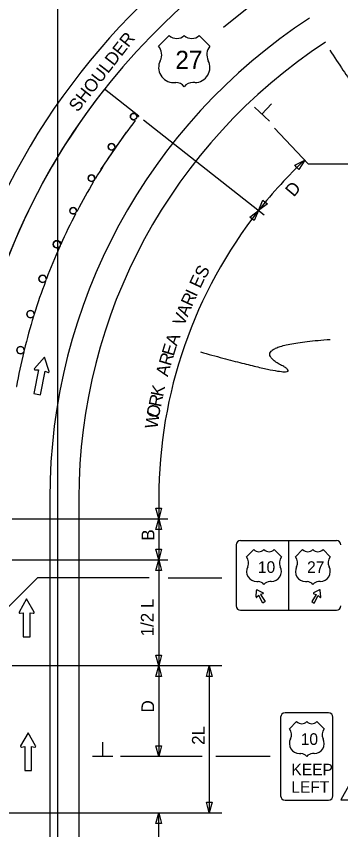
# Model space of a CAD drawing. Extents: x 16486 to 19505, y 5576 to 6998.
# Drawn here: x 16981.9 to 17160.6, y 6297.8 to 6745.9 of the extents above; entities that cross this region are included whole.
import ezdxf

# ---------------------------------------------------------------- set-up
doc = ezdxf.new("R2010")
doc.units = 0
for name, color, linetype in [('ALI_LEGAL_EX', 7, 'Continuous'), ('MT_SCRATCH_LEVEL_A', 7, 'Continuous'), ('MT_SCRATCH_LEVEL_E', 7, 'Continuous'), ('PAVT_EDGE_EX', 7, 'Continuous'), ('TRAFFIC_SIGNS_PR', 7, 'Continuous'), ('TYPICAL_EX', 7, 'Continuous'), ('TYPICAL_TEXT_DIMEN_PR', 7, 'Continuous')]:
    doc.layers.add(name, color=color, linetype=linetype)

msp = doc.modelspace()

# ---------------------------------------------------------------- linework, layer by layer
at = {"layer": 'ALI_LEGAL_EX'}
for p, q in [((17004.68, 6974.12), (17004.68, 6155.98)), ((17004.68, 6922.21), (17004.68, 6058.3))]:
    msp.add_line(p, q, dxfattribs=at)
for points in [[(17096.1, 6739.95), (17115.56, 6755.65)], [(17028.47, 6661.47), (17042.59, 6682.1)], [(17028.47, 6661.47), (17042.59, 6682.1)]]:
    msp.add_lwpolyline(points, dxfattribs=at)
at = {"layer": 'MT_SCRATCH_LEVEL_A'}
for points in [[(17049.36, 6690.98), (17030.51, 6705.83)], [(17047.47, 6688.56), (17047.02, 6688.91)], [(17048.36, 6690.77), (17049.21, 6690.79)], [(17036.22, 6674.06), (17036.65, 6673.76)], [(17035.5, 6672.09), (17035.08, 6672.38)], [(17025.1, 6656.76), (17025.49, 6656.52)], [(17024.54, 6654.94), (17024.15, 6655.17)], [(17015.04, 6638.82), (17015.4, 6638.63)], [(17014.63, 6637.16), (17014.27, 6637.35)], [(17006.27, 6620.31), (17006.43, 6620.24)], [(17005.76, 6618.76), (17005.6, 6618.83)], [(16998.06, 6599.94), (16997.94, 6599.98)], [(16998.43, 6601.3), (16998.55, 6601.25)], [(16991.49, 6580.69), (16991.4, 6580.72)], [(16991.75, 6581.84), (16991.84, 6581.82)], [(16986.25, 6562.02), (16986.31, 6562.01)], [(16986.08, 6561.09), (16986.02, 6561.1)], [(16981.95, 6541.91), (16981.99, 6541.9)]]:
    msp.add_lwpolyline(points, dxfattribs=at)
for centre, radius, start, end in [((17316.4, 6480.53), 364, 141.7598, 180), ((17046.56, 6690.66), 1.8, 3.5129, 180), ((17316.4, 6480.53), 340, 142.2759, 145.3661), ((17046.56, 6690.66), 1.8, 180, 284.5518), ((17316.4, 6480.53), 340, 141.7598, 141.7992), ((17034.42, 6674.06), 1.8, 0, 180), ((17034.42, 6674.06), 1.8, 180, 291.4148), ((17316.4, 6480.53), 340, 145.7074, 148.8275), ((17023.3, 6656.76), 1.8, 0, 180), ((17023.3, 6656.76), 1.8, 180, 298.2766), ((17316.4, 6480.53), 340, 149.1383, 152.2895), ((17013.24, 6638.82), 1.8, 0, 180), ((17013.24, 6638.82), 1.8, 180, 305.1374), ((17316.4, 6480.53), 340, 152.5687, 155.7382), ((17004.27, 6620.31), 2, 0, 180), ((17004.27, 6620.31), 2, 180, 312.0242), ((17316.4, 6480.53), 340, 156.0121, 159.2032), ((16996.43, 6601.3), 2, 0, 180), ((17316.4, 6480.53), 340, 159.4399, 162.6687), ((16996.43, 6601.3), 2, 180, 318.8797), ((16989.75, 6581.84), 2, 0, 180), ((17316.4, 6480.53), 340, 162.8672, 166.1345), ((16989.75, 6581.84), 2, 180, 325.7344), ((16984.25, 6562.02), 2, 0, 180), ((16984.25, 6562.02), 2, 180, 332.5884), ((17316.4, 6480.53), 340, 166.2942, 169.6006)]:
    msp.add_arc(centre, radius, start, end, dxfattribs=at)
at = {"layer": 'MT_SCRATCH_LEVEL_E'}
for p, q in [((16997.4, 6558.21), (16991.97, 6551.9)), ((17000.07, 6550.31), (16997.4, 6558.21)), ((16994.11, 6551.1), (16991.55, 6538.09)), ((16992.31, 6551.13), (16994.11, 6551.1)), ((16995.23, 6537.37), (16997.78, 6550.38)), ((16997.78, 6550.38), (16999.47, 6549.73)), ((16991.55, 6538.09), (16995.23, 6537.37)), ((16987.65, 6424.96), (16983.54, 6417.72)), ((16991.8, 6417.72), (16987.65, 6424.96)), ((16984.02, 6417.03), (16985.8, 6417.35)), ((16985.8, 6417.35), (16985.8, 6404.09)), ((16989.54, 6404.09), (16989.54, 6417.35)), ((16989.54, 6417.35), (16991.32, 6417.03)), ((16985.8, 6404.09), (16989.54, 6404.09)), ((16988.45, 6351.23), (16984.34, 6343.99)), ((16992.6, 6343.99), (16988.45, 6351.23)), ((16984.82, 6343.31), (16986.6, 6343.62)), ((16986.6, 6343.62), (16986.6, 6330.36)), ((16990.34, 6330.36), (16990.34, 6343.62)), ((16990.34, 6343.62), (16992.12, 6343.31)), ((16986.6, 6330.36), (16990.34, 6330.36))]:
    msp.add_line(p, q, dxfattribs=at)
for centre, start, end in [((16992.32, 6551.6), 139.3091, 268.8481), ((16999.62, 6550.16), 248.9205, 18.6574), ((16983.95, 6417.49), 150.4248, 279.9638), ((16991.39, 6417.49), 260.0362, 29.7731), ((16984.75, 6343.76), 150.4248, 279.9638), ((16992.19, 6343.76), 260.0362, 29.7731)]:
    msp.add_arc(centre, 0.463, start, end, dxfattribs=at)
at = {"layer": 'PAVT_EDGE_EX'}
for p, q in [((17000.4, 6480.53), (17000.4, 6125.9)), ((17016.4, 6480.53), (17016.4, 6125.9))]:
    msp.add_line(p, q, dxfattribs=at)
for radius, start, end in [(380, 123.1879, 163.0483), (364, 123.1879, 180), (316, 123.1879, 180), (300, 123.1879, 180), (300, 180, 180.00000277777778)]:
    msp.add_arc((17316.4, 6480.53), radius, start, end, dxfattribs=at)
at = {"layer": 'TRAFFIC_SIGNS_PR'}
for p, q in [((17102.95, 6454.67), (17102.95, 6421.07)), ((17105.35, 6457.07), (17158.15, 6457.07)), ((17131.75, 6457.07), (17131.75, 6418.67)), ((17113.93, 6426.02), (17114.22, 6429.65)), ((17114.59, 6429.86), (17117.87, 6428.3)), ((17148.92, 6429.86), (17145.64, 6428.3)), ((17149.57, 6426.02), (17149.29, 6429.65)), ((17105.35, 6418.67), (17158.15, 6418.67)), ((17127.49, 6359.71), (17127.49, 6316.51)), ((17153.89, 6362.11), (17129.89, 6362.11)), ((17156.29, 6316.51), (17156.29, 6359.71)), ((17129.89, 6314.11), (17153.89, 6314.11))]:
    msp.add_line(p, q, dxfattribs=at)
for points in [[(17117.83, 6427.81), (17116.42, 6427.42), (17118.93, 6423.44), (17117.6, 6422.67), (17115.41, 6426.84), (17114.37, 6425.82)], [(17145.68, 6427.81), (17147.09, 6427.42), (17144.57, 6423.44), (17145.9, 6422.67), (17148.09, 6426.84), (17149.13, 6425.82)]]:
    msp.add_lwpolyline(points, dxfattribs=at)
for centre, radius in [((17046.56, 6690.66), 1.8), ((17034.42, 6674.06), 1.8), ((17023.3, 6656.76), 1.8), ((17013.24, 6638.82), 1.8), ((17004.27, 6620.31), 2), ((16996.43, 6601.3), 2), ((16989.75, 6581.84), 2), ((16984.25, 6562.02), 2)]:
    msp.add_circle(centre, radius, dxfattribs=at)
for centre, radius, start, end in [((17105.35, 6454.67), 2.4, 90, 180), ((17105.35, 6454.67), 2.4, 90, 180), ((17158.15, 6454.67), 2.4, 0, 90), ((17114.47, 6429.63), 0.26, 64.4823, 175.5177), ((17117.75, 6428.06), 0.26, 285.9885, 64.4823), ((17145.75, 6428.06), 0.26, 115.5177, 254.0115), ((17149.03, 6429.63), 0.26, 4.4823, 115.5177), ((17114.19, 6426), 0.26, 175.5177, 314.0115), ((17149.31, 6426), 0.26, 225.9885, 4.4823), ((17105.35, 6421.07), 2.4, 180, 270), ((17158.15, 6421.07), 2.4, 270, 0), ((17129.89, 6359.71), 2.4, 90, 180), ((17153.89, 6359.71), 2.4, 0, 90), ((17129.89, 6316.51), 2.4, 180, 270), ((17153.89, 6316.51), 2.4, 270, 0)]:
    msp.add_arc(centre, radius, start, end, dxfattribs=at)
at = {"layer": 'TYPICAL_EX'}
for p, q in [((17060.28, 6729.51), (17066.18, 6735.4)), ((17088.58, 6729.51), (17082.68, 6735.4)), ((17068.53, 6709.45), (17069.71, 6709.45)), ((17080.33, 6709.45), (17079.15, 6709.45)), ((17108.7, 6448.07), (17112.7, 6452.07)), ((17127.9, 6448.07), (17123.9, 6452.07)), ((17135.6, 6448.07), (17139.6, 6452.07)), ((17154.8, 6448.07), (17150.8, 6452.07)), ((17114.3, 6434.46), (17115.1, 6434.46)), ((17122.31, 6434.46), (17121.51, 6434.46)), ((17141.2, 6434.46), (17142, 6434.46)), ((17149.21, 6434.46), (17148.41, 6434.46)), ((17132.29, 6353.31), (17136.29, 6357.31)), ((17151.49, 6353.31), (17147.49, 6357.31)), ((17137.88, 6339.7), (17138.68, 6339.7)), ((17145.89, 6339.7), (17145.09, 6339.7))]:
    msp.add_line(p, q, dxfattribs=at)
for centre, radius, start, end in [((17070.3, 6739.69), 5.96, 226.1404, 313.8596), ((17078.56, 6739.69), 5.96, 226.1404, 313.8596), ((17054.69, 6724.78), 7.31, 333.0977, 40.1936), ((17094.17, 6724.78), 7.31, 139.8064, 206.9023), ((17068.54, 6717.69), 8.24, 152.6698, 269.9013), ((17080.32, 6717.69), 8.24, 270.0987, 27.3302), ((17069.72, 6703.54), 5.91, 37.1038, 90.1385), ((17079.14, 6703.54), 5.91, 89.8615, 142.8962), ((17115.5, 6454.99), 4.04, 226.1404, 313.8596), ((17121.1, 6454.99), 4.04, 226.1404, 313.8596), ((17142.4, 6454.99), 4.04, 226.1404, 313.8596), ((17148, 6454.99), 4.04, 226.1404, 313.8596), ((17104.91, 6444.87), 4.96, 333.0977, 40.1936), ((17131.69, 6444.87), 4.96, 139.8064, 206.9023), ((17131.81, 6444.87), 4.96, 333.0977, 40.1936), ((17158.59, 6444.87), 4.96, 139.8064, 206.9023), ((17114.31, 6440.06), 5.59, 152.6698, 269.9013), ((17122.3, 6440.06), 5.59, 270.0987, 27.3302), ((17141.21, 6440.06), 5.59, 152.6698, 269.9013), ((17149.2, 6440.06), 5.59, 270.0987, 27.3302), ((17115.11, 6430.46), 4.01, 37.1038, 90.1385), ((17121.5, 6430.46), 4.01, 89.8615, 142.8962), ((17142.01, 6430.46), 4.01, 37.1038, 90.1385), ((17148.4, 6430.46), 4.01, 89.8615, 142.8962), ((17139.09, 6360.22), 4.04, 226.1404, 313.8596), ((17144.69, 6360.22), 4.04, 226.1404, 313.8596), ((17128.49, 6350.11), 4.96, 333.0977, 40.1936), ((17155.28, 6350.11), 4.96, 139.8064, 206.9023), ((17137.89, 6345.29), 5.59, 152.6698, 269.9013), ((17145.88, 6345.29), 5.59, 270.0987, 27.3302), ((17138.69, 6335.69), 4.01, 37.1038, 90.1385), ((17145.08, 6335.69), 4.01, 89.8615, 142.8962)]:
    msp.add_arc(centre, radius, start, end, dxfattribs=at)
at = {"layer": 'TYPICAL_TEXT_DIMEN_PR'}
for p, q in [((17121.33, 6688.23), (17113.09, 6695.89)), ((17117.21, 6692.06), (17122.51, 6697.77)), ((17052.06, 6688.84), (17118.33, 6636.62)), ((17124.09, 6684.37), (17142.7, 6664.64)), ((17135.38, 6663.86), (17140.72, 6666.74)), ((17140.72, 6666.74), (17137.53, 6661.57)), ((17142.7, 6664.64), (17175.9, 6664.64)), ((17142.7, 6664.64), (17175.9, 6664.64)), ((17142.7, 6664.64), (17175.9, 6664.64)), ((17136.46, 6662.71), (17135.38, 6663.86)), ((17137.53, 6661.57), (17136.46, 6662.71)), ((17115.33, 6638.99), (17117.73, 6644.56)), ((17120.19, 6642.62), (17115.33, 6638.99)), ((17117.73, 6644.56), (17118.96, 6643.59)), ((17118.96, 6643.59), (17120.19, 6642.62)), ((17110.47, 6635.35), (17115.33, 6638.99)), ((17115.33, 6638.99), (17112.94, 6633.41)), ((17111.7, 6634.38), (17110.47, 6635.35)), ((17112.94, 6633.41), (17111.7, 6634.38)), ((17006.91, 6621.31), (17005.09, 6622.14)), ((17060.4, 6480.53), (17060.4, 6469.09)), ((17060.4, 6469.09), (17058.83, 6474.95)), ((17058.83, 6474.95), (17060.4, 6474.95)), ((17060.4, 6474.95), (17061.97, 6474.95)), ((17061.97, 6474.95), (17060.4, 6469.09)), ((16979.6, 6469.09), (17065.4, 6469.09)), ((17058.83, 6463.22), (17060.4, 6469.09)), ((17060.4, 6469.09), (17060.4, 6446.53)), ((17060.4, 6469.09), (17061.97, 6463.22)), ((17060.4, 6463.22), (17058.83, 6463.22)), ((17061.97, 6463.22), (17060.4, 6463.22)), ((17060.4, 6446.53), (17058.83, 6452.39)), ((17058.83, 6452.39), (17060.4, 6452.39)), ((17060.4, 6452.39), (17061.97, 6452.39)), ((17061.97, 6452.39), (17060.4, 6446.53)), ((16979.6, 6446.53), (17065.4, 6446.53)), ((17058.83, 6440.67), (17060.4, 6446.53)), ((17060.4, 6446.53), (17060.4, 6388.14)), ((17060.4, 6446.53), (17061.97, 6440.67)), ((17060.4, 6440.67), (17058.83, 6440.67)), ((17061.97, 6440.67), (17060.4, 6440.67)), ((16970.24, 6413.2), (16993.65, 6436.53)), ((17055.09, 6436.53), (16993.65, 6436.53)), ((17065.63, 6436.53), (17095.19, 6436.53)), ((17060.4, 6388.14), (17058.83, 6394)), ((17058.83, 6394), (17060.4, 6394)), ((17060.4, 6394), (17061.97, 6394)), ((17061.97, 6394), (17060.4, 6388.14)), ((17095.19, 6388.14), (16979.6, 6388.14)), ((17058.83, 6382.28), (17060.4, 6388.14)), ((17060.4, 6388.14), (17061.97, 6382.28)), ((17060.4, 6388.14), (17060.4, 6338.14)), ((17086.64, 6382.28), (17088.21, 6388.14)), ((17088.21, 6388.14), (17088.21, 6307.03)), ((17088.21, 6388.14), (17089.78, 6382.28)), ((17060.4, 6382.28), (17058.83, 6382.28)), ((17061.97, 6382.28), (17060.4, 6382.28)), ((17088.21, 6382.28), (17086.64, 6382.28)), ((17089.78, 6382.28), (17088.21, 6382.28)), ((17029.53, 6338.14), (17029.53, 6345.93)), ((17060.4, 6338.14), (17058.83, 6344)), ((17058.83, 6344), (17060.4, 6344)), ((17060.4, 6344), (17061.97, 6344)), ((17061.97, 6344), (17060.4, 6338.14)), ((17035.15, 6338.14), (17023.9, 6338.14)), ((17084.21, 6338.14), (17039.4, 6338.14)), ((17121.69, 6338.14), (17091.83, 6338.14)), ((17088.21, 6307.03), (17086.64, 6312.89)), ((17086.64, 6312.89), (17088.21, 6312.89)), ((17088.21, 6312.89), (17089.78, 6312.89)), ((17089.78, 6312.89), (17088.21, 6307.03)), ((16955.45, 6307.03), (17095.19, 6307.03)), ((17058.83, 6301.17), (17060.4, 6307.03)), ((17060.4, 6278.47), (17060.4, 6307.03)), ((17060.4, 6307.03), (17061.97, 6301.17)), ((17060.4, 6301.17), (17058.83, 6301.17)), ((17061.97, 6301.17), (17060.4, 6301.17))]:
    msp.add_line(p, q, dxfattribs=at)
msp.add_lwpolyline([(17165.05, 6322.07), (17160.53, 6314.24), (17169.58, 6314.24)], close=True, dxfattribs=at)
for start, end in [(133.334, 141.7597), (141.7599, 180)]:
    msp.add_arc((17316.4, 6480.53), 256, start, end, dxfattribs=at)
for points in [[(17154.48, 6727.28), (17192.72, 6669.11), (17169.5, 6734.81), (17198.86, 6725.23)], [(17083.35, 6560.99), (17146.59, 6543.42), (17107.77, 6564.76), (17154.73, 6567.9)]]:
    msp.add_open_spline(points, degree=2, dxfattribs=at)

# ---------------------------------------------------------------- texts
at = {"layer": 'TRAFFIC_SIGNS_PR'}
for s, p in [('10', (17114.96, 6439.27)), ('27', (17142.03, 6439.27)), ('10', (17138.55, 6344.51)), ('KEEP', (17133.42, 6327.71)), ('LEFT', (17133.34, 6318.11))]:
    msp.add_text(s, height=6.4, dxfattribs=at).set_placement(p)
at = {"layer": 'TYPICAL_EX'}
msp.add_text('27', height=10, dxfattribs=at).set_placement((17069.54, 6716.93))
at = {"layer": 'TYPICAL_TEXT_DIMEN_PR'}
for s, rotation, p in [('SHOULDER', 52.0184, (17015.76, 6692.73)), ('D', 50, (17134.74, 6646.01)), ('S', 62.4974, (17085.93, 6600.91)), ('E', 65.1772, (17083.24, 6595.61)), ('R', 65.1772, (17078.58, 6585.54)), ('I', 65.1772, (17081.08, 6590.96)), ('A', 67.857, (17076.3, 6579.94)), ('V', 67.857, (17074.2, 6574.78)), ('A', 70.5368, (17070.32, 6563.9)), ('E', 73.2167, (17068.57, 6558.32)), ('R', 73.2167, (17066.95, 6552.92)), ('A', 75.8965, (17065.37, 6547.08)), ('K', 78.5763, (17062.72, 6535.95)), ('R', 78.5763, (17061.58, 6530.32)), ('O', 81.2562, (17060.5, 6524.36)), ('W', 81.2562, (17059.57, 6518.33)), ('B', 90, (17057.97, 6457.04)), ('1/2 L', 90, (17057.54, 6404.27)), ('D', 90, (17057.84, 6362.36)), ('2L', 90, (17085.65, 6344.53))]:
    msp.add_text(s, height=7, rotation=rotation, dxfattribs=at).set_placement(p)

doc.saveas('drawing.dxf')
